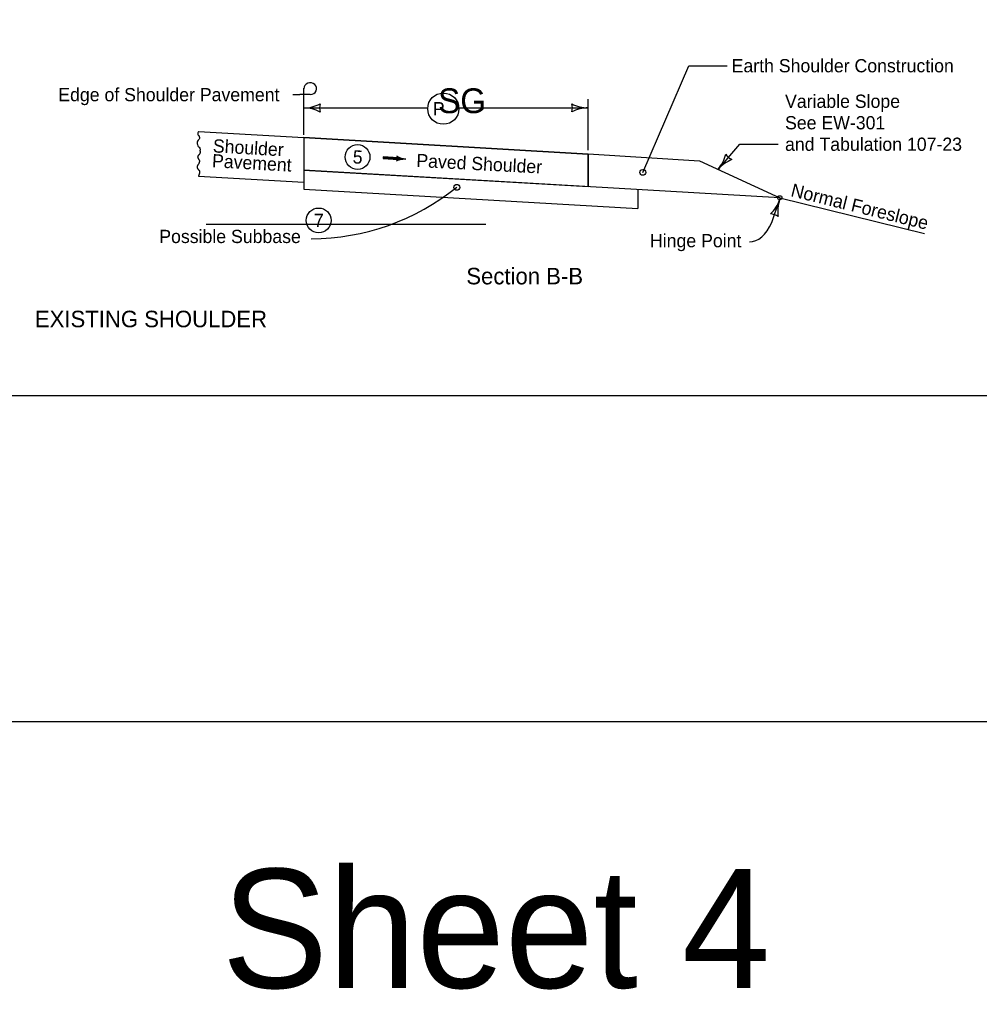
# Model space of a CAD drawing. Extents: x 9538 to 81668, y 7600 to 11751.
# Drawn here: x 21860 to 23022, y 7600 to 8774 of the extents above; entities that cross this region are included whole.
import ezdxf

# ---------------------------------------------------------------- set-up
doc = ezdxf.new("R2010")
doc.units = 0
for name, color, linetype in [('Default', 7, 'Continuous'), ('DsnShtMinorGrid13', 7, 'Continuous'), ('DsnShtMinorGrid14', 7, 'Continuous'), ('dsnStdDimension', 7, 'Continuous'), ('dsnStdNote', 7, 'Continuous'), ('dsnStdShading', 7, 'Continuous'), ('dsnStdTable', 7, 'Continuous'), ('Level 13', 7, 'Continuous')]:
    doc.layers.add(name, color=color, linetype=linetype)

msp = doc.modelspace()

# ---------------------------------------------------------------- linework, layer by layer
at = {"layer": 'Default'}
msp.add_lwpolyline([(20932.5, 9944), (24067.5, 9944), (24067.5, 7924), (20932.5, 7924)], close=True, dxfattribs=at)
at = {"layer": 'DsnShtMinorGrid13'}
for centre in [(22269.2, 8607.5), (22222.2, 8530.8)]:
    msp.add_circle(centre, 15, dxfattribs=at)
at = {"layer": 'DsnShtMinorGrid14'}
for centre in [(22614.3, 8588.9), (22389.3, 8570.8)]:
    msp.add_circle(centre, 3.54, dxfattribs=at)
at = {"layer": 'dsnStdDimension'}
for p, q in [((22548.3, 8615.7), (22548.3, 8677.4)), ((22204, 8666.9), (22354, 8666.9)), ((22391.9, 8667), (22548.3, 8667))]:
    msp.add_line(p, q, dxfattribs=at)
msp.add_circle((22373, 8666), 18.9, dxfattribs=at)
for centre, radius, start, end in [((22204, 8709.4), 42.5, 270, 298.0725), ((22204, 8624.4), 42.5, 61.9275, 90), ((22239.7, 8666.9), 16.4, 162.2666, 197.7334), ((22512.7, 8667), 16.4, 342.2666, 17.7333), ((22548.3, 8709.5), 42.5, 241.9275, 270), ((22548.3, 8624.5), 42.5, 90, 118.0725), ((22212.6, 8790.7), 282, 270.132, 308.7946)]:
    msp.add_arc(centre, radius, start, end, dxfattribs=at)
at = {"layer": 'dsnStdNote'}
for p, q in [((22614.3, 8588.9), (22670, 8718)), ((22670, 8718), (22716.4, 8718)), ((22204, 8670.2), (22204, 8691)), ((22190.7, 8683), (22199.4, 8683)), ((22211.9, 8683), (22199.4, 8683)), ((22204, 8634.2), (22204, 8670.2)), ((22705.3, 8592.6), (22731.9, 8623)), ((22731.9, 8623), (22778.2, 8623)), ((22318.3, 8605.6), (22300.1, 8606.6)), ((22318.3, 8606.6), (22318.3, 8606.6)), ((22318.2, 8604.7), (22318.2, 8604.7)), ((22770.4, 8528.4), (22779.9, 8555.9))]:
    msp.add_line(p, q, dxfattribs=at)
for points in [[(22318.3, 8606.5), (22300.2, 8607.6), (22300.1, 8605.7), (22318.2, 8604.7), (22318.3, 8606.3), (22300.4, 8607.4), (22300.3, 8605.9), (22317.8, 8604.9), (22318, 8606), (22300.6, 8607.1), (22300.6, 8606.1), (22317.6, 8605.1), (22317.7, 8605.8), (22300.8, 8606.9), (22300.8, 8606.3), (22317.4, 8605.4)], [(22317.9, 8607.8), (22318.6, 8606.6), (22318.6, 8605), (22317.9, 8603.6), (22320.6, 8604.4), (22323.8, 8605.1), (22324.7, 8605.2), (22322.5, 8605.8), (22319.2, 8607), (22318.3, 8607.5), (22318.4, 8604), (22323.4, 8605.2), (22318.7, 8606.8), (22318.7, 8604.4), (22322.1, 8605.3), (22319.1, 8606.2), (22318.9, 8604.8), (22321.1, 8605.3), (22319.5, 8605.8), (22319.3, 8605.2), (22320.1, 8605.3)]]:
    msp.add_lwpolyline(points, dxfattribs=at)
for centre, radius, start, end in [((22673.3, 8620.6), 42.5, 318.8454, 346.9178), ((22728.7, 8619.4), 16.4, 211.112, 246.5787), ((22737.3, 8564.6), 42.5, 110.7729, 138.8454), ((22739.7, 8569.7), 42.5, 312.9788, 341.0513), ((22820.1, 8542.1), 42.5, 161.0513, 189.1238), ((22768.3, 8522.2), 16.4, 53.3179, 88.7846)]:
    msp.add_arc(centre, radius, start, end, dxfattribs=at)
for centre, major_axis, ratio, start_param, end_param in [((22211.9, 8690.2), (-7.81, 0), 0.913811, 1.570796, 6.283185), ((22314.6, 8605.8), (3.88, 0), 0.913811, 5.202895, 7.237436), ((22329.6, 8625.2), (-22.2, 0), 0.913811, 0.954258, 1.478381), ((22326.8, 8584.8), (22.2, 0), 0.913811, 1.537172, 2.061295), ((22743.3, 8566.2), (0, 61.5), 0.559383, 3.141593, 4.048985)]:
    msp.add_ellipse(centre, major_axis=major_axis, ratio=ratio, start_param=start_param, end_param=end_param, dxfattribs=at)
at = {"layer": 'dsnStdShading'}
msp.add_line((20947.5, 8319), (24043.2, 8319), dxfattribs=at)
at = {"layer": 'dsnStdTable'}
for p, q in [((22076.6, 8638.5), (22204, 8631.1)), ((22204, 8631.1), (22204, 8577.1)), ((22204, 8631.1), (22548.3, 8611.1)), ((22548.3, 8611.1), (22204, 8631.1)), ((22204, 8631.1), (22204, 8591.5)), ((22547.9, 8611.3), (22547.9, 8611.3)), ((22548.3, 8611.2), (22683.1, 8602.8)), ((22548.3, 8571.7), (22548.3, 8611.1)), ((22548.3, 8611.1), (22548.3, 8571.7)), ((22683.1, 8602.8), (22780.1, 8558.3)), ((22076.6, 8584.5), (22204, 8577.1)), ((22780.1, 8558.3), (22204, 8591.5)), ((22204, 8591.5), (22548.3, 8571.7)), ((22204, 8577.1), (22204, 8568.7)), ((22204, 8568.7), (22608.3, 8545.4)), ((22608.3, 8568.2), (22608.3, 8545.4)), ((22780.1, 8558.3), (22955.1, 8515)), ((22086, 8526.2), (22424.5, 8526.2))]:
    msp.add_line(p, q, dxfattribs=at)
msp.add_circle((22269.2, 8607.5), 15, dxfattribs=at)
msp.add_ellipse((22780.1, 8558.3), major_axis=(2.58, 0), ratio=0.913811, dxfattribs=at)
for points in [[(22076.6, 8638.5), (22076.1, 8634.9), (22077.1, 8633.4), (22078, 8631.1), (22077.4, 8629.1), (22075.5, 8626.7), (22075, 8624.8), (22075.5, 8622.5), (22076.3, 8620.1), (22077.4, 8619.4), (22078.8, 8616.9), (22078.8, 8616)], [(22076.8, 8598.9), (22077, 8599.2), (22077.2, 8599.4), (22077.6, 8600), (22077.8, 8600.6), (22078, 8600.9), (22078.1, 8601.2), (22078.2, 8601.8), (22078.2, 8602.4), (22078.2, 8603), (22078.1, 8603.3), (22078.1, 8603.4), (22078, 8603.6), (22077.8, 8603.9), (22077.6, 8604.3), (22077.3, 8604.7), (22077, 8605.1), (22076.9, 8605.3), (22076.7, 8605.6), (22076.5, 8606.2), (22076.3, 8606.8), (22076.2, 8607.1), (22076.1, 8607.4), (22076.1, 8607.5), (22076.1, 8607.6), (22076.3, 8608.4), (22076.5, 8608.9), (22076.7, 8609.4), (22077.2, 8610.1), (22077.7, 8610.6), (22078.2, 8611.1), (22078.5, 8611.4), (22078.7, 8611.8), (22078.9, 8612.3), (22079, 8612.7), (22079.1, 8613.2), (22079.1, 8613.5), (22079.2, 8613.6), (22079.2, 8613.7), (22079.1, 8614.2), (22079, 8614.7), (22078.9, 8614.8), (22078.9, 8615), (22078.8, 8615.1), (22078.8, 8615.2), (22078.8, 8616)], [(22076.8, 8598.9), (22076.6, 8598.7), (22076.3, 8598.4), (22076.1, 8598.2), (22075.9, 8597.9), (22075.8, 8597.6), (22075.6, 8597.4), (22075.4, 8596.8), (22075.3, 8596.5), (22075.2, 8596.2), (22075.1, 8595.9), (22075.1, 8595.8), (22075, 8595.6), (22075.1, 8595.1), (22075.2, 8594.6), (22075.4, 8594.1), (22075.7, 8593.6), (22076.1, 8592.9), (22076.6, 8592.4), (22077.1, 8591.8), (22077.4, 8591.5), (22077.6, 8591.2), (22078, 8590.2), (22078.1, 8589.8), (22078.1, 8589.3), (22078, 8589), (22078, 8588.7), (22077.9, 8588.4), (22077.9, 8588.1), (22077.6, 8587), (22077.4, 8586.4), (22077.2, 8585.8), (22077, 8585.2), (22076.8, 8584.9), (22076.7, 8584.6), (22076.6, 8584.5)]]:
    msp.add_spline(points, degree=3, dxfattribs=at)

# ---------------------------------------------------------------- texts
at = {"layer": 'DsnShtMinorGrid13'}
msp.add_text('5', height=16, rotation=356.6997, dxfattribs=at).set_placement((22263, 8599.9))
msp.add_text('7', height=16, dxfattribs=at).set_placement((22216.4, 8522.8))
at = {"layer": 'dsnStdDimension'}
for s, height, p in [('SG', 30, (22366.7, 8660.6)), ('P', 16, (22360.2, 8658))]:
    msp.add_text(s, height=height, dxfattribs=at).set_placement(p)
at = {"layer": 'dsnStdNote'}
for s, height, p in [('Earth Shoulder Construction', 16, (22721.8, 8710)), ('Edge of Shoulder Pavement', 16, (21907.1, 8675)), ('Variable Slope', 16, (22786.4, 8667)), ('See EW-301', 16, (22786.4, 8641)), ('and Tabulation 107-23', 16, (22786.4, 8615)), ('Possible Subbase', 16, (22029.3, 8503.4)), ('Hinge Point', 16, (22623, 8498.3)), ('Section B-B', 20, (22400.8, 8453.4)), ('EXISTING SHOULDER', 20, (21878.8, 8401.5))]:
    msp.add_text(s, height=height, dxfattribs=at).set_placement(p)
for s, rotation, p in [('Shoulder', 356.7346, (22093.8, 8613.2)), ('Pavement', 356.7346, (22092.8, 8595.2)), ('Paved Shoulder ', 356.983, (22340, 8595.5)), ('Normal Foreslope', 346.0988, (22792.4, 8560.3))]:
    msp.add_text(s, height=16, rotation=rotation, dxfattribs=at).set_placement(p)
at = {"layer": 'Level 13'}
msp.add_text('Sheet 4', height=144, dxfattribs=at).set_placement((22104.9, 7602))

doc.saveas('drawing.dxf')
